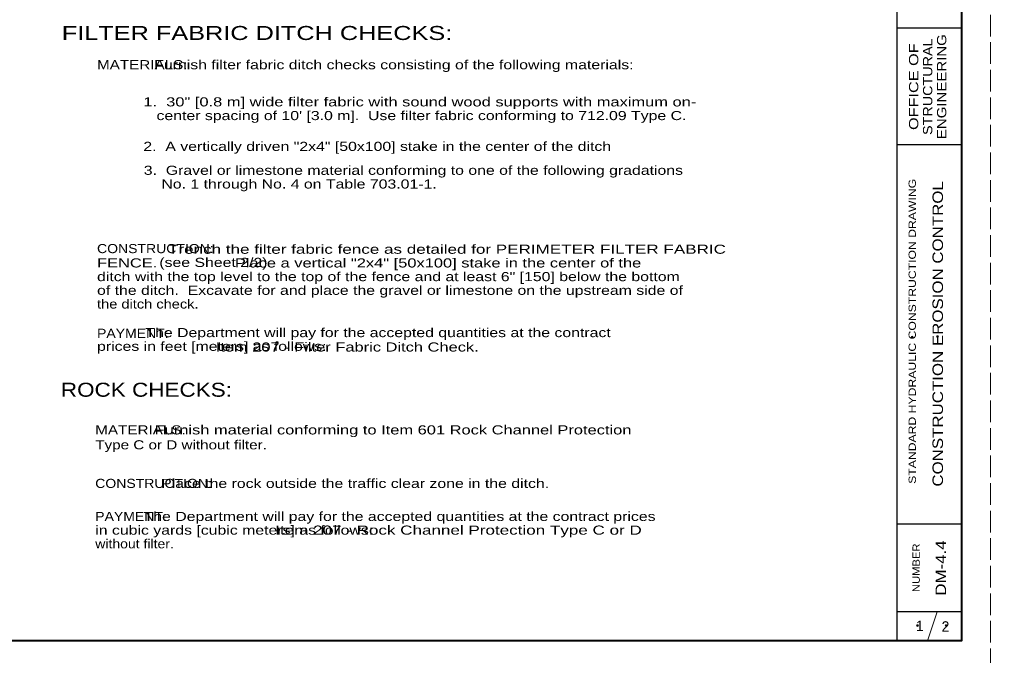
# Model space of a CAD drawing. Extents: x 1083.1 to 1117.1, y 672.5 to 716.5.
# Drawn here: x 1100.48 to 1117.13, y 694.76 to 705.66 of the extents above; entities that cross this region are included whole.
import ezdxf
from ezdxf.enums import TextEntityAlignment as Align

# ---------------------------------------------------------------- set-up
doc = ezdxf.new("R2010")
doc.units = 0
doc.header["$LTSCALE"] = 0.062
doc.header["$PDMODE"] = 32
doc.header["$PDSIZE"] = 0.031
doc.linetypes.add('LONG_DASHED', pattern=[7.5, 6, -1.5])
doc.layers.add('1', color=7, linetype='Continuous', lineweight=13)

msp = doc.modelspace()

# ---------------------------------------------------------------- linework, layer by layer
at = {"layer": '1', "lineweight": 25}
for p, q in [((1115.52642, 695.00825), (1115.52642, 716.00825)), ((1116.62642, 716.00825), (1116.62642, 695.00825)), ((1116.62642, 705.50825), (1115.52642, 705.50825)), ((1116.62642, 703.50825), (1115.52642, 703.50825)), ((1116.62642, 697.00825), (1115.52642, 697.00825)), ((1116.62642, 695.50825), (1115.52642, 695.50825))]:
    msp.add_line(p, q, dxfattribs=at)
at = {"layer": '1'}
msp.add_line((1116.04308, 695.00825), (1116.20975, 695.50825), dxfattribs=at)
at = {"layer": '1', "linetype": 'LONG_DASHED'}
msp.add_lwpolyline([(1083.12642, 694.50825), (1117.12642, 694.50825), (1117.12642, 716.50825), (1083.12642, 716.50825)], close=True, dxfattribs=at)
at = {"layer": '1', "lineweight": 25}
msp.add_lwpolyline([(1116.62642, 695.00825), (1085.12642, 695.00825), (1085.12642, 716.00825)], dxfattribs=at)
at = {"layer": '1', "lineweight": 40}
msp.add_lwpolyline([(1085.12642, 716.00825), (1116.62642, 716.00825), (1116.62642, 695.00825), (1085.12642, 695.00825)], close=True, dxfattribs=at)
msp.add_lwpolyline([(1085.12642, 716.00825), (1116.62642, 716.00825), (1116.62642, 695.00825), (1085.12642, 695.00825)], close=True, dxfattribs=at)
at = {"layer": '1'}
for p in [(1115.78383, 700.21425), (1116.21667, 700.22158), (1115.8745, 695.272), (1116.36292, 695.271)]:
    msp.add_point(p, dxfattribs=at)

# ---------------------------------------------------------------- texts
for s, height, width, p in [('FILTER FABRIC DITCH CHECKS:', 0.24, 1.35, (1101.20942, 705.30283)), ('             Furnish filter fabric ditch checks consisting of the following materials:', 0.156, 1.3, (1101.81433, 704.8015)), ('MATERIALS:', 0.156, 1.25, (1101.81433, 704.8015)), ('1.  30" [0.8 m] wide filter fabric with sound wood supports with maximum on-', 0.156, 1.35, (1102.60767, 704.16517)), ("   center spacing of 10' [3.0 m].  Use filter fabric conforming to 712.09 Type C.", 0.156, 1.3, (1102.60767, 703.9305)), ('2.  A vertically driven "2x4" [50x100] stake in the center of the ditch', 0.156, 1.3, (1102.60767, 703.40267)), ('3.  Gravel or limestone material conforming to one of the following gradations', 0.156, 1.3, (1102.6155, 702.993)), ('    No. 1 through No. 4 on Table 703.01-1.', 0.156, 1.3, (1102.6155, 702.75833)), ('CONSTRUCTION:', 0.156, 1.15, (1101.81425, 701.65183)), ('               Trench the filter fabric fence as detailed for PERIMETER FILTER FABRIC', 0.156, 1.4, (1101.81425, 701.641)), ('FENCE.                 Place a vertical "2x4" [50x100] stake in the center of the ', 0.156, 1.35, (1101.81425, 701.40633)), ('(see Sheet 2/2)', 0.156, 1.3, (1102.88133, 701.4155)), ('ditch with the top level to the top of the fence and at least 6" [150] below the bottom ', 0.156, 1.3, (1101.81425, 701.17167)), ('of the ditch.  Excavate for and place the gravel or limestone on the upstream side of ', 0.156, 1.3, (1101.81425, 700.937)), ('the ditch check.', 0.156, 1.2, (1101.81425, 700.70233)), ('PAYMENT:', 0.156, 1.15, (1101.81433, 700.20067)), ('           The Department will pay for the accepted quantities at the contract ', 0.156, 1.3, (1101.81433, 700.21292)), ('prices in feet [meters] as follows: ', 0.156, 1.3, (1101.81433, 699.97825)), ('                                       Item 207 - Filter Fabric Ditch Check.', 0.156, 1.35, (1100.79625, 699.966)), ('ROCK CHECKS:', 0.24, 1.2, (1101.19417, 699.19192)), ('MATERIALS:', 0.156, 1.25, (1101.78367, 698.5465)), ('             Furnish material conforming to Item 601 Rock Channel Protection', 0.156, 1.35, (1101.78367, 698.5465)), ('Type C or D without filter.', 0.156, 1.25, (1101.78367, 698.2905)), ('CONSTRUCTION:', 0.156, 1.15, (1101.78358, 697.62958)), ('               Place the rock outside the traffic clear zone in the ditch.', 0.156, 1.3, (1101.78358, 697.62958)), ('PAYMENT:', 0.156, 1.15, (1101.78358, 697.06392)), ('           The Department will pay for the accepted quantities at the contract prices', 0.156, 1.3, (1101.78358, 697.06392)), ('in cubic yards [cubic meters] as follows:', 0.156, 1.3, (1101.78358, 696.82925)), ('                                      Item 207 - Rock Channel Protection Type C or D', 0.156, 1.4, (1101.78358, 696.82925)), ('without filter.', 0.156, 1.15, (1101.78358, 696.59525))]:
    msp.add_text(s, height=height, dxfattribs=dict(at, width=width)).set_placement(p)
for s, height, width, p in [('STRUCTURAL', 0.16, 1.15, (1116.12817, 704.50271)), ('ENGINEERING', 0.16, 1.2, (1116.36817, 704.50279)), ('OFFICE OF', 0.16, 1.3, (1115.88817, 704.50271)), ('STANDARD HYDRAULIC CONSTRUCTION DRAWING', 0.125, 1.25, (1115.84633, 700.31229)), ('CONSTRUCTION EROSION CONTROL', 0.18, 1.2, (1116.31142, 700.26837)), ('NUMBER', 0.125, 1.15, (1115.91342, 696.26233)), ('DM-4.4', 0.18, 1.2, (1116.36342, 696.25854))]:
    msp.add_text(s, height=height, rotation=90, dxfattribs=dict(at, width=width)).set_placement(p, align=Align.CENTER)
for s, p in [('1', (1115.91427, 695.17833)), ('2', (1116.35371, 695.16575))]:
    msp.add_text(s, height=0.18, dxfattribs=at).set_placement(p, align=Align.CENTER)

doc.saveas('drawing.dxf')
